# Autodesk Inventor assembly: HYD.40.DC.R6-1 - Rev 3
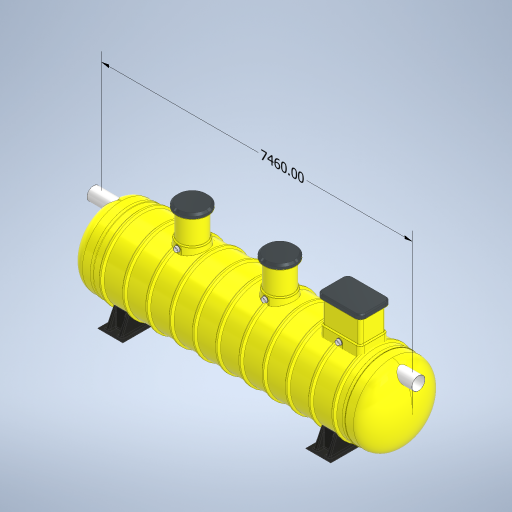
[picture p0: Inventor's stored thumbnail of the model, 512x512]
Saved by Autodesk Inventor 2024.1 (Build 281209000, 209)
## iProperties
Created: 2023-08
Part Number: HYD.40.DC.R6-1 - Rev 3
Document SubType Name: Assembly
Designer: macga
Author: macga
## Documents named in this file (43)
- D:\$ Protector Vault\Workspace\Automation Files\1. Protector Stardard Products\HydroProtectors\FAMILY\HYD.40 - Vernon\HYD.40.DC.R6-1 - Rev 3.iam
- D:\$ Protector Vault\Workspace\1. Protector Stardard Products\HydroProtectors\FAMILY\HORIZONTAL TANK - IPART\HORIZONTAL TANK - IPART.ipt
- D:\$ Protector Vault\Workspace\1. Protector Stardard Products\HydroProtectors\FAMILY\DOME - IPART\DOME - IPART\SU.DOME.1850-9.ipt
- D:\$ Protector Vault\Workspace\1. Protector Stardard Products\HydroProtectors\FAMILY\DOME - IPART\DOME - IPART.ipt
- D:\$ Protector Vault\Workspace\1. Protector Stardard Products\HydroProtectors\FAMILY\FOOT - IPART\FRP Foot - IPART\SU.HS.FOOT.1850.ipt
- D:\$ Protector Vault\Workspace\1. Protector Stardard Products\HydroProtectors\FAMILY\FOOT - IPART\FRP Foot - IPART.ipt
- D:\$ Protector Vault\Workspace\1. Protector Stardard Products\HydroProtectors\FAMILY\HYD.BAFFLE - IPART\SU.BAFFLE.1850\SU.BAFFLE.1850.ipt
- D:\$ Protector Vault\Workspace\1. Protector Stardard Products\HydroProtectors\FAMILY\HYD.BAFFLE - IPART\SU.BAFFLE.1850.ipt
- D:\$ Protector Vault\Workspace\1. Protector Stardard Products\HydroProtectors\FAMILY\ACD Base - IPART\SU.ACDBASE.1850\SU.ACDBASE.1850-300ACDFV.ipt
- D:\$ Protector Vault\Workspace\1. Protector Stardard Products\HydroProtectors\FAMILY\ACD Base - IPART\SU.ACDBASE.1850.ipt
- D:\$ Protector Vault\Workspace\1. Protector Stardard Products\HydroProtectors\FAMILY\ACDTUBE - IPART\ACDTUBE - IPART\ACDTUBE.300-1880.ipt
- D:\$ Protector Vault\Workspace\1. Protector Stardard Products\HydroProtectors\FAMILY\ACDTUBE - IPART\ACDTUBE - IPART.ipt
- D:\$ Protector Vault\Workspace\1. Protector Stardard Products\HydroProtectors\FAMILY\ACD FLOAT VALVE - IPART\ACD.FloatValve - IASSY\ACD.FVALVE.300.ASSY.iam
- D:\$ Protector Vault\Workspace\1. Protector Stardard Products\HydroProtectors\FAMILY\ACD FLOAT VALVE - IPART\ACD.FloatValve - IASSY.iam
- D:\$ Protector Vault\Workspace\1. Protector Stardard Products\HydroProtectors\FAMILY\SU.600Dia Manway Adaptor - IPART\Horizontal 600mmDia Manway Adaptor (FLANGED) SU.MWA.HS.6R-1850-1850\SU.MWA.HS.6R-1850.ipt
- D:\$ Protector Vault\Workspace\1. Protector Stardard Products\HydroProtectors\FAMILY\SU.600Dia Manway Adaptor - IPART\SU.MWA.HS.6R - IPART.ipt
- D:\$ Protector Vault\Workspace\1. Protector Stardard Products\HydroProtectors\FAMILY\WIN.600mmDiaManwayRiser - IPART\600mmDia Manway Riser.ipt
- D:\$ Protector Vault\Workspace\1. Protector Stardard Products\HydroProtectors\Automation Files\600mmDia Manway Cover.ipt
- D:\$ Protector Vault\Workspace\1. Protector Stardard Products\HydroProtectors\HYD.50 300 Outlet Vertical.ipt
- D:\$ Protector Vault\Workspace\1. Protector Stardard Products\HydroProtectors\FAMILY\OUTLET ELBOW - IPART\OUTLET ELBOW - IPART.ipt
- D:\$ Protector Vault\Workspace\1. Protector Stardard Products\HydroProtectors\Coalescer Guide Rail.ipt
- D:\$ Protector Vault\Workspace\1. Protector Stardard Products\HydroProtectors\ISO 4065 Pipe DN315x2.5xS63 - 1365.ipt
- D:\$ Protector Vault\Workspace\1. Protector Stardard Products\HydroProtectors\FAMILY\INLET PIPE ELBOW- IPART\INLET PIPE ELBOW- IPART\InletPipeElbow.300D.ipt
- D:\$ Protector Vault\Workspace\1. Protector Stardard Products\HydroProtectors\FAMILY\INLET PIPE ELBOW- IPART\INLET PIPE ELBOW- IPART.ipt
- D:\$ Protector Vault\Workspace\1. Protector Stardard Products\HydroProtectors\Upper Guide Rai Braket.ipt
- D:\$ Protector Vault\Workspace\1. Protector Stardard Products\Standard Components\Flanged Vent.ipt
- D:\$ Protector Vault\Workspace\1. Protector Stardard Products\HydroProtectors\HYD Oil Probe\Oil Probe Assembly.iam
- D:\$ Protector Vault\Workspace\1. Protector Stardard Products\Xtremeprotector\Vault\Chain.ipt
- D:\$ Protector Vault\Workspace\1. Protector Stardard Products\Xtremeprotector\Vault\Lifting Eye.ipt
- D:\$ Protector Vault\Workspace\1. Protector Stardard Products\HydroProtectors\FAMILY\OUTLET ELBOW - IPART\OUTLET ELBOW - IPART\OutletPipeElbow.300D-100DCoupling.ipt
- D:\$ Protector Vault\Workspace\1. Protector Stardard Products\HydroProtectors\FAMILY\WIN.600mmDiaManwayRiser - IPART\600mmDia Manway Riser\SU.600mmDia.ManwayRiser.600-10.ipt
- D:\$ Protector Vault\Workspace\1. Protector Stardard Products\HydroProtectors\FAMILY\Coalescer Guide Rail-014.ipt
- D:\$ Protector Vault\Workspace\1. Protector Stardard Products\HydroProtectors\FAMILY\COALESCER FILTER - IPART\CF-R6.iam
- D:\$ Protector Vault\Workspace\1. Protector Stardard Products\Xtremeprotector\Vault\Chain\Chain-30.ipt
- D:\$ Protector Vault\Workspace\1. Protector Stardard Products\HydroProtectors\FAMILY\HORIZONTAL TANK - IPART\HORIZONTAL TANK - IPART\WIN.HB.1850x6110L-9.ipt
- D:\$ Protector Vault\Workspace\1. Protector Stardard Products\HydroProtectors\FAMILY\CF.BASE - IPART\CF BASE SINGLE - IPART\SU.CFBASE.1850\SU.CFBASE1.1850.R6-R5-R4-R3-R2 - PART\SU.CFBASE1.1850.SINGLE-R6.300-OP.ipt
- D:\$ Protector Vault\Workspace\1. Protector Stardard Products\HydroProtectors\FAMILY\CF.BASE - IPART\CF BASE SINGLE - IPART\SU.CFBASE.1850\SU.CFBASE1.1850.R6-R5-R4-R3-R2 - PART.ipt
- D:\$ Protector Vault\Workspace\1. Protector Stardard Products\HydroProtectors\FAMILY\600x900mm Manway Adaptor - IPART\600x900mm Manway Adaptor - IPART\SU.MRADAPTOR.1850.600Lx900W.ipt
- D:\$ Protector Vault\Workspace\1. Protector Stardard Products\HydroProtectors\FAMILY\600x900mm Manway Adaptor - IPART\600x900mm Manway Adaptor - IPART.ipt
- D:\$ Protector Vault\Workspace\1. Protector Stardard Products\Standard Components\600x900 - 600mm Manway Riser.ipt
- D:\$ Protector Vault\Workspace\Automation Files\600x900mm Manway Cover ST B and D\600x900mm Manway Cover-D.ipt
- D:\$ Protector Vault\Workspace\Automation Files\600x900mm Manway Cover ST B and D.ipt
- D:\$ Protector Vault\Workspace\1. Protector Stardard Products\Trade Waste Sampling Point Assembly 300.iam
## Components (34 placed, 26 different names)
1. WIN.HB.1850x6110L-9:1
2. SU.DOME.1850-9:1 — Mate:1, Mate:3, Mate:10, Mate:88, Angle:8, Angle:9
3. SU.DOME.1850-9:2 — Mate:2, Mate:4, Angle:4, Angle:9
4. SU.HS.FOOT.1850:1 — Mate:5, Mate:6
5. SU.HS.FOOT.1850:2 — Mate:7, Mate:8
6. SU.BAFFLE.1850:1 — Mate:9, Mate:10, Mate:12
7. SU.ACDBASE.1850-300ACDFV:1 — Mate:11, Mate:12, Mate:13, Mate:14
8. ACDTUBE.300-1880:1 — Mate:13, Mate:14, Mate:15, Mate:38
9. ACD.FVALVE.300.ASSY:1 [sub-assembly] — Mate:15
10. SU.CFBASE1.1850.SINGLE-R6.300-OP:1 — Flush:7, Mate:104, Mate:105
11. CF-R6:1 [sub-assembly] — Mate:104, Mate:105
12. SU.600mmDia.ManwayRiser.600-10:1 — Mate:30, Mate:31, Mate:40, Mate:41, Flush:2
13. 600mmDia Manway Cover:2 — Mate:30, Mate:31, Angle:2
14. HYD.50 300 Outlet Vertical:1 — Mate:36, Mate:37
15. OutletPipeElbow.300D-100DCoupling:2 — Mate:36, Mate:37, Mate:53, Mate:54, Angle:4
16. SU.MWA.HS.6R-1850:2
17. Coalescer Guide Rail-014:1
18. ISO 4065 Pipe DN315x2.5xS63 - 1365:2 — Mate:88
19. ISO 4065 Pipe DN315x2.5xS63 - 1365:1 — Mate:53, Mate:54, Mate:106, Mate:107
20. InletPipeElbow.300D:1
21. 600x900 - 600mm Manway Riser:1
22. 600x900mm Manway Cover-D:1 — Mate:61, Flush:4, Angle:1, Flush:13
23. Upper Guide Rai Braket:1 — Mate:103
24. Flanged Vent:2 — Mate:68, Mate:69
25. Flanged Vent:3
26. SU.MRADAPTOR.1850.600Lx900W:1
27. Oil Probe Assembly:1 [sub-assembly] — Mate:87, Flush:12, Angle:5, Angle:12, Angle:13
28. Chain-30:4 — Tangent:5
29. Lifting Eye:1 — Mate:79, Mate:85, Mate:86, Tangent:5
30. SU.MWA.HS.6R-1850:3 — Mate:91, Mate:92, Angle:10, Mate:87, Angle:11, Angle:5, Angle:12, Mate:93, Mate:94, Mate:97, Mate:98
31. Flanged Vent:4 — Mate:93, Mate:94
32. SU.600mmDia.ManwayRiser.600-10:2 — Mate:97, Mate:98
33. 600mmDia Manway Cover:3
34. Trade Waste Sampling Point Assembly 300:1 [sub-assembly] — Mate:106, Mate:107
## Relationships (59: Mate 43, Angle 10, Flush 5, Tangent 1)
- Mate:1: SU.DOME.1850-9:1
- Mate:2: SU.DOME.1850-9:2
- Mate:3: SU.DOME.1850-9:1
- Mate:4: SU.DOME.1850-9:2
- Mate:5: SU.HS.FOOT.1850:1
- Mate:6: SU.HS.FOOT.1850:1
- Mate:7: SU.HS.FOOT.1850:2
- Mate:8: SU.HS.FOOT.1850:2
- Mate:9: SU.BAFFLE.1850:1
- Mate:10: SU.DOME.1850-9:1 ↔ SU.BAFFLE.1850:1
- Mate:11: SU.ACDBASE.1850-300ACDFV:1
- Mate:12: SU.BAFFLE.1850:1 ↔ SU.ACDBASE.1850-300ACDFV:1
- Mate:13: SU.ACDBASE.1850-300ACDFV:1 ↔ ACDTUBE.300-1880:1
- Mate:14: SU.ACDBASE.1850-300ACDFV:1 ↔ ACDTUBE.300-1880:1
- Mate:15: ACDTUBE.300-1880:1 ↔ ACD.FVALVE.300.ASSY:1
- Mate:30: SU.600mmDia.ManwayRiser.600-10:1 ↔ 600mmDia Manway Cover:2
- Mate:31: SU.600mmDia.ManwayRiser.600-10:1 ↔ 600mmDia Manway Cover:2
- Mate:36: HYD.50 300 Outlet Vertical:1 ↔ OutletPipeElbow.300D-100DCoupling:2
- Mate:37: HYD.50 300 Outlet Vertical:1 ↔ OutletPipeElbow.300D-100DCoupling:2
- Angle:11: SU.MWA.HS.6R-1850:3
- Mate:38: ACDTUBE.300-1880:1
- Mate:40: SU.600mmDia.ManwayRiser.600-10:1
- Mate:41: SU.600mmDia.ManwayRiser.600-10:1
- Mate:53: OutletPipeElbow.300D-100DCoupling:2 ↔ ISO 4065 Pipe DN315x2.5xS63 - 1365:1
- Mate:54: OutletPipeElbow.300D-100DCoupling:2 ↔ ISO 4065 Pipe DN315x2.5xS63 - 1365:1
- Flush:2: SU.600mmDia.ManwayRiser.600-10:1
- Mate:61: 600x900mm Manway Cover-D:1
- Flush:4: 600x900mm Manway Cover-D:1
- Mate:68: Flanged Vent:2
- Mate:69: Flanged Vent:2
- Flush:7: SU.CFBASE1.1850.SINGLE-R6.300-OP:1
- Angle:1: 600x900mm Manway Cover-D:1
- Angle:2: 600mmDia Manway Cover:2
- Mate:79: Lifting Eye:1
- Angle:4: SU.DOME.1850-9:2 ↔ OutletPipeElbow.300D-100DCoupling:2
- Mate:85: Lifting Eye:1
- Mate:86: Lifting Eye:1
- Tangent:5: Chain-30:4 ↔ Lifting Eye:1
- Mate:87: Oil Probe Assembly:1 ↔ SU.MWA.HS.6R-1850:3
- Flush:12: Oil Probe Assembly:1
- Angle:5: Oil Probe Assembly:1 ↔ SU.MWA.HS.6R-1850:3
- Mate:88: SU.DOME.1850-9:1 ↔ ISO 4065 Pipe DN315x2.5xS63 - 1365:2
- Flush:13: 600x900mm Manway Cover-D:1
- Angle:8: SU.DOME.1850-9:1
- Angle:9: SU.DOME.1850-9:1 ↔ SU.DOME.1850-9:2
- Mate:91: SU.MWA.HS.6R-1850:3
- Mate:92: SU.MWA.HS.6R-1850:3
- Angle:10: SU.MWA.HS.6R-1850:3
- Angle:12: Oil Probe Assembly:1 ↔ SU.MWA.HS.6R-1850:3
- Angle:13: Oil Probe Assembly:1
- Mate:93: SU.MWA.HS.6R-1850:3 ↔ Flanged Vent:4
- Mate:94: SU.MWA.HS.6R-1850:3 ↔ Flanged Vent:4
- Mate:97: SU.MWA.HS.6R-1850:3 ↔ SU.600mmDia.ManwayRiser.600-10:2
- Mate:98: SU.MWA.HS.6R-1850:3 ↔ SU.600mmDia.ManwayRiser.600-10:2
- Mate:103: Upper Guide Rai Braket:1
- Mate:104: SU.CFBASE1.1850.SINGLE-R6.300-OP:1 ↔ CF-R6:1
- Mate:105: SU.CFBASE1.1850.SINGLE-R6.300-OP:1 ↔ CF-R6:1
- Mate:106: ISO 4065 Pipe DN315x2.5xS63 - 1365:1 ↔ Trade Waste Sampling Point Assembly 300:1
- Mate:107: ISO 4065 Pipe DN315x2.5xS63 - 1365:1 ↔ Trade Waste Sampling Point Assembly 300:1
## Named parameters: d190_d36 = 0, d191_d37 = 0
